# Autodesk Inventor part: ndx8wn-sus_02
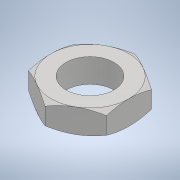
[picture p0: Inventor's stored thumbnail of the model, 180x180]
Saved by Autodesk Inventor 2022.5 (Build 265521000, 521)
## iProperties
Part Number: ndx8wn-sus_02
Material: 一般
Document SubType Name: Modeling
Designer: ImaoCorp
Density: 1 g/cm^3
Appearance: 既定
Author: ImaoCorp
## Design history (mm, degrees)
feature "ndx8wn-sus_02"
node "ソリッド1"
